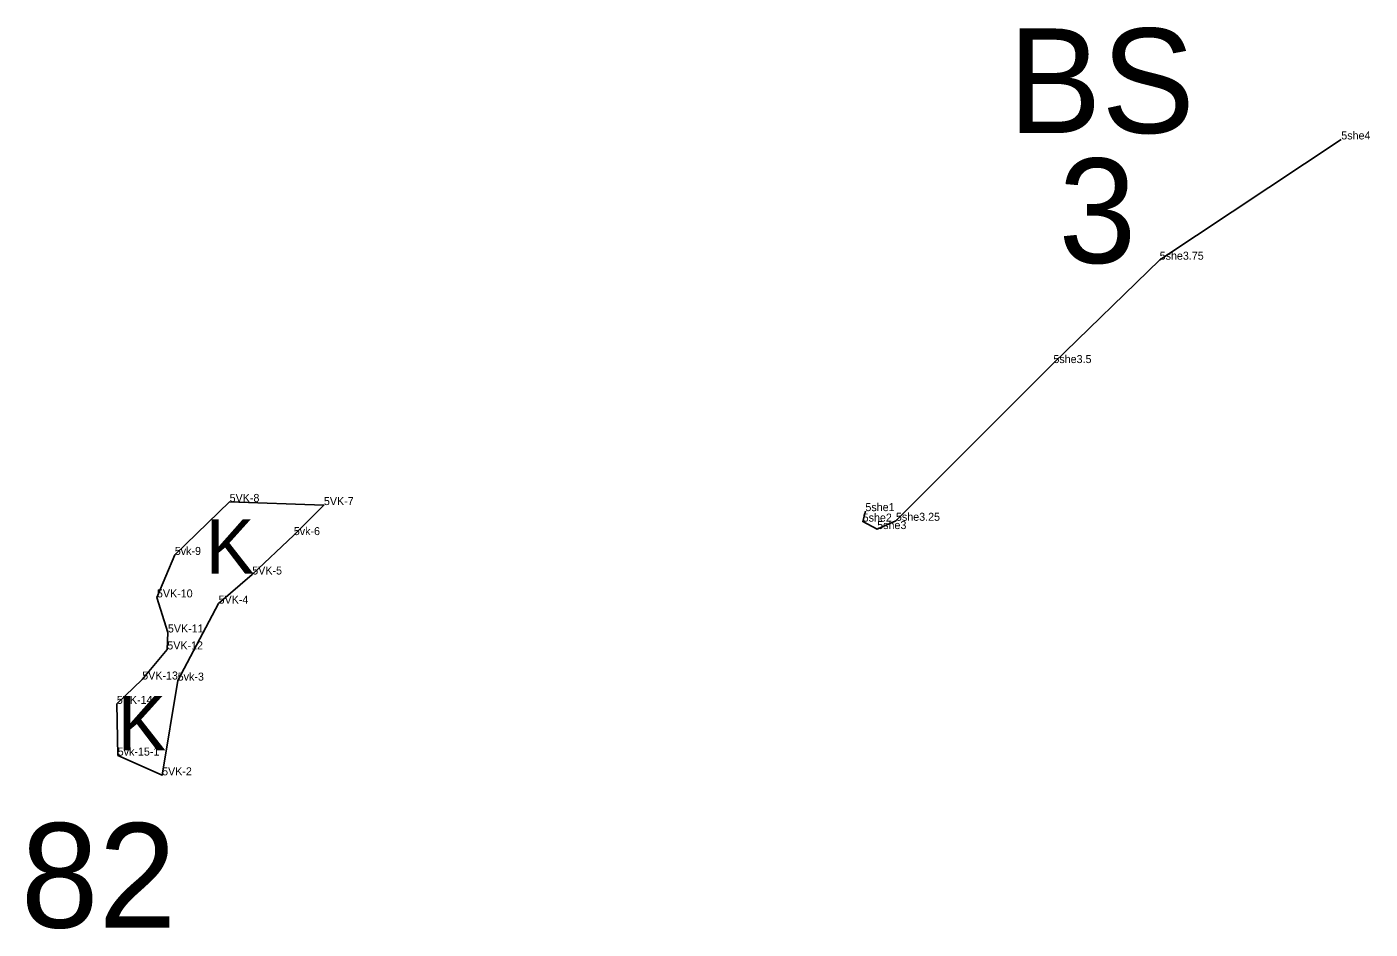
# Model space of a CAD drawing. Extents: x 2072529 to 2268796, y 436423 to 470406.
# Drawn here: x 2125478 to 2126318, y 447082 to 447645 of the extents above; entities that cross this region are included whole.
import ezdxf

# ---------------------------------------------------------------- set-up
doc = ezdxf.new("R2010")
doc.units = 0
for name, color, linetype in [('Default', 7, 'Continuous'), ('Exist Environmental Wetland Boundary Cogo Comment', 7, 'Continuous'), ('Exist Environmental Wetland Boundary Cogo Point CELL', 7, 'Continuous'), ('Exist Hydro Jurisdictional Stream or Body of Water NEU Mitigable Cogo Comment', 7, 'Continuous'), ('Old_Level_20', 7, 'Continuous'), ('Old_Level_52', 7, 'Continuous')]:
    doc.layers.add(name, color=color, linetype=linetype)

msp = doc.modelspace()

# ---------------------------------------------------------------- linework, layer by layer
at = {"layer": 'Old_Level_20'}
for p, q in [((2126299.91, 447574.98), (2126299.91, 447574.98)), ((2126186.41, 447499.84), (2126186.41, 447499.84)), ((2126120, 447435.27), (2126120, 447435.27)), ((2125605.21, 447348.52), (2125605.21, 447348.52)), ((2125664.12, 447346.55), (2125664.12, 447346.55)), ((2126002.51, 447342.77), (2126002.51, 447342.77)), ((2126000.81, 447336.24), (2126000.81, 447336.24)), ((2126021.62, 447336.74), (2126021.62, 447336.74)), ((2125645.31, 447327.79), (2125645.31, 447327.79)), ((2126009.9, 447331.56), (2126009.9, 447331.56)), ((2125570.94, 447315.42), (2125570.94, 447315.42)), ((2125619.35, 447303.18), (2125619.35, 447303.18)), ((2125559.78, 447288.87), (2125559.78, 447288.87)), ((2125598.32, 447284.99), (2125598.32, 447284.99)), ((2125566.63, 447266.97), (2125566.63, 447266.97)), ((2125566.26, 447256.36), (2125566.26, 447256.36)), ((2125550.57, 447237.59), (2125550.57, 447237.59)), ((2125572.76, 447236.89), (2125572.76, 447236.89)), ((2125534.71, 447222.37), (2125534.71, 447222.37)), ((2125535.27, 447190.03), (2125535.27, 447190.03)), ((2125563.01, 447177.73), (2125563.01, 447177.73))]:
    msp.add_line(p, q, dxfattribs=at)
msp.add_lwpolyline([(2125535.27, 447190.03), (2125534.71, 447222.37), (2125550.57, 447237.59), (2125566.26, 447256.36), (2125566.63, 447266.97), (2125559.78, 447288.87), (2125570.94, 447315.42), (2125605.21, 447348.52), (2125664.12, 447346.55), (2125645.31, 447327.79), (2125619.35, 447303.18), (2125598.32, 447284.99), (2125572.76, 447236.89), (2125563.01, 447177.73)], close=True, dxfattribs=at)
at = {"layer": 'Old_Level_52'}
msp.add_lwpolyline([(2126002.51, 447342.77), (2126000.81, 447336.24), (2126009.9, 447331.56), (2126021.62, 447336.74), (2126120, 447435.27), (2126186.41, 447499.84), (2126299.91, 447574.98)], dxfattribs=at)

# ---------------------------------------------------------------- texts
at = {"layer": 'Default'}
for s, p in [('BS', (2126091.78, 447578.99)), ('3', (2126123.2, 447497.78)), ('82', (2125474.69, 447082.57))]:
    msp.add_text(s, height=65.34, dxfattribs=at).set_placement(p)
at = {"layer": 'Exist Environmental Wetland Boundary Cogo Comment'}
for s, p in [('5VK-8', (2125605.21, 447348.52)), ('5VK-7', (2125664.12, 447346.55)), ('5vk-6', (2125645.31, 447327.79)), ('5vk-9', (2125570.94, 447315.42)), ('5VK-5', (2125619.35, 447303.18)), ('5VK-10', (2125559.78, 447288.87)), ('5VK-4', (2125598.32, 447284.99)), ('5VK-11', (2125566.63, 447266.97)), ('5VK-12', (2125566.26, 447256.36)), ('5VK-13', (2125550.57, 447237.59)), ('5vk-3', (2125572.76, 447236.89)), ('5VK-14', (2125534.71, 447222.37)), ('5vk-15-1', (2125535.27, 447190.03)), ('5VK-2', (2125563.01, 447177.73))]:
    msp.add_text(s, height=5, dxfattribs=at).set_placement(p)
at = {"layer": 'Exist Environmental Wetland Boundary Cogo Point CELL'}
for p in [(2125590.33, 447303.64), (2125535.18, 447193.34)]:
    msp.add_text('K', height=34, dxfattribs=at).set_placement(p)
at = {"layer": 'Exist Hydro Jurisdictional Stream or Body of Water NEU Mitigable Cogo Comment'}
for s, p in [('5she4', (2126299.91, 447574.98)), ('5she3.75', (2126186.41, 447499.84)), ('5she3.5', (2126120, 447435.27)), ('5she2', (2126000.81, 447336.24)), ('5she1', (2126002.51, 447342.77)), ('5she3.25', (2126021.62, 447336.74)), ('5she3', (2126009.9, 447331.56))]:
    msp.add_text(s, height=5, dxfattribs=at).set_placement(p)

doc.saveas('drawing.dxf')
